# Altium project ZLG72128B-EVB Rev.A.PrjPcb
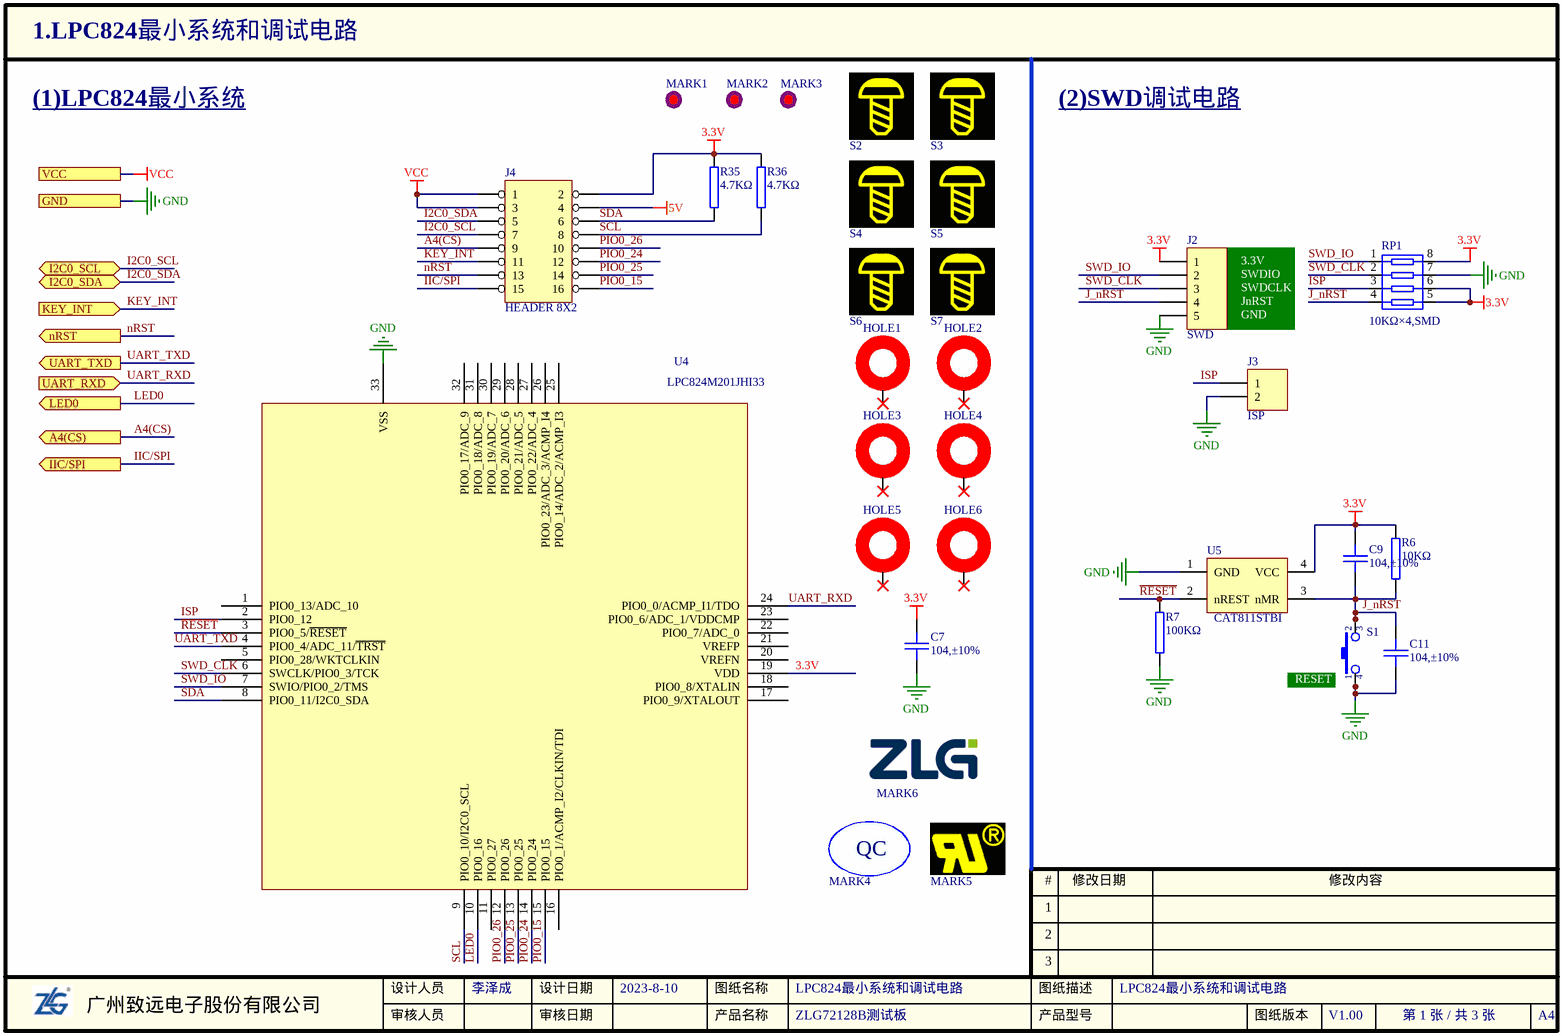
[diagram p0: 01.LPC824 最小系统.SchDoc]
3 sheets, 109 parts. Net scope: flat (ports and power ports of the same name join across sheets).
Board file: ZLG72128B-EVB Rev.A.PcbDoc
Sheets:
  01.LPC824 最小系统.SchDoc
  02.ZLG72128B-key-digital.SchDoc
  03.USB和电源.SchDoc

## Sheet 01.LPC824 最小系统.SchDoc
size A4; Author: 李泽成; DocumentNumber: 1; SheetNumber: 1; SheetTotal: 3; PageSetup: Record=PageOptions¦CenterHorizontal=True¦CenterVertical=True¦PrintScale=1.00¦XCorrection=1.00¦YCorrection=1.00¦PrintKind=0¦BorderSize=5000000¦LeftOffset=0¦BottomOffset=0¦Orientation=2¦PaperLength=1000¦PaperWidth=1000¦Scale=100¦PaperSource=7¦PrintQuality=600¦MediaType=1¦DitherType=10¦PaperKind=A4¦PrintScaleMode=1; DesignDate: 2023-8-10; SheetName: LPC824最小系统和调试电路; SheetVersion: V1.00; SheetDescription: LPC824最小系统和调试电路; ProductName: ZLG72128B测试板

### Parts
C7  104,±10%  [0603C]
C9  104,±10%  [0603C]
C11  104,±10%  [0603C]
HOLE1  HOLE  [HOLE-3.8]  (value not drawn)  (no BOM)
HOLE2  HOLE  [HOLE-3.8]  (value not drawn)  (no BOM)
HOLE3  HOLE  [HOLE-3.8]  (value not drawn)  (no BOM)
HOLE4  HOLE  [HOLE-3.8]  (value not drawn)  (no BOM)
HOLE5  HOLE  [HOLE-3.8]  (value not drawn)  (no BOM)
HOLE6  HOLE  [HOLE-3.8]  (value not drawn)  (no BOM)
J2  SWD  [SIP2.54-1X5]
J3  ISP  [SIP2.54-1X2]
J4  HEADER 8X2  [IDC-16-2.54]
MARK1  MARKER  [MARKER-C-1.0M]  (value not drawn)  (no BOM)
MARK2  MARKER  [MARKER-C-1.0M]  (value not drawn)  (no BOM)
MARK3  MARKER  [MARKER-C-1.0M]  (value not drawn)  (no BOM)
MARK4  ZY QC  [ZY_QC]  (value not drawn)  (no BOM)
MARK5  UR  [ZY_UR-3X2]  (value not drawn)  (no BOM)
MARK6  ZLGLOGO  [ZLG0.5]  (value not drawn)  (no BOM)
R6  10KΩ  [0603R]
R7  100KΩ  [0603R]
R35  4.7KΩ  [0603R]
R36  4.7KΩ  [0603R]
RP1  10KΩ×4,SMD  [0603RA]
S1  6×6×5.0mm,红色  [KEY-6S]  (value not drawn)
S2  (no value)  [Screw-Mark2]  (no BOM)
S3  (no value)  [Screw-Mark2]  (no BOM)
S4  (no value)  [Screw-Mark2]  (no BOM)
S5  (no value)  [Screw-Mark2]  (no BOM)
S6  (no value)  [Screw-Mark2]  (no BOM)
S7  (no value)  [Screw-Mark2]  (no BOM)
U4  LPC824M201JHI33  [QFN50P500X500X85-33N]
U5  value CAT811STBI  [SOT-143]  (hidden comment: CAT811)

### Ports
A4(CS) (out), GND, I2C0_SCL (bidir), I2C0_SDA (bidir), IIC/SPI (out), KEY_INT (in), LED0 (out), nRST (out), UART_RXD (in), UART_TXD (out), VCC

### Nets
3.3V: C7.2 C9.2 J2.1 J4.2 R6.2 R35.2 R36.2 RP1.5 RP1.6 RP1.8 U4.19(VDD) U5.4(VCC)
5V: J4.4
GND: C7.1 C11.1 J2.5 J3.2 R7.1 RP1.7 S1.1 S1.4 U4.33(VSS) U5.1(GND) ; port GND
VCC: J4.1 J4.3 ; port VCC
A4(CS): J4.9 ; port A4(CS)
I2C0_SCL: J4.7 ; port I2C0_SCL
I2C0_SDA: J4.5 ; port I2C0_SDA
IIC/SPI: J4.15 ; port IIC/SPI
ISP: J3.1 RP1.3 U4.2(PIO0_12)
J_nRST: C9.1 C11.2 J2.4 R6.1 RP1.4 S1.2 S1.3 U5.3(nMR)
KEY_INT: J4.11 ; port KEY_INT
LED0: U4.10(PIO0_16) ; port LED0
nRST: J4.13 ; port nRST
PIO0_15: J4.16 U4.15(PIO0_15)
PIO0_24: J4.12 U4.14(PIO0_24)
PIO0_25: J4.14 U4.13(PIO0_25)
PIO0_26: J4.10 U4.12(PIO0_26)
~{RESET}: R7.2 U4.3(PIO0_5/~{RESET}) U5.2(nREST)
SCL: J4.8 R36.1 U4.9(PIO0_10/I2C0_SCL)
SDA: J4.6 R35.1 U4.8(PIO0_11/I2C0_SDA)
SWD_CLK: J2.3 RP1.2 U4.6(SWCLK/PIO0_3/TCK)
SWD_IO: J2.2 RP1.1 U4.7(SWIO/PIO0_2/TMS)
UART_RXD: U4.24(PIO0_0/ACMP_I1/TDO) ; port UART_RXD
UART_TXD: U4.4(PIO0_4/ADC_11/~{TRST}) ; port UART_TXD

Not connected (* = marked no-connect by the designer): HOLE1 1*; HOLE2 1*; HOLE3 1*; HOLE4 1*; HOLE5 1*; HOLE6 1*; MARK1 0; MARK2 0; MARK3 0; U4 1(PIO0_13/ADC_10) 5(PIO0_28/WKTCLKIN) 11(PIO0_27) 16(PIO0_1/ACMP_I2/CLKIN/TDI) 17(PIO0_9/XTALOUT) 18(PIO0_8/XTALIN) 20(VREFN) 21(VREFP) 22(PIO0_7/ADC_0) 23(PIO0_6/ADC_1/VDDCMP) 25(PIO0_14/ADC_2/ACMP_I3) 26(PIO0_23/ADC_3/ACMP_I4) 27(PIO0_22/ADC_4) 28(PIO0_21/ADC_5) 29(PIO0_20/ADC_6) 30(PIO0_19/ADC_7) 31(PIO0_18/ADC_8) 32(PIO0_17/ADC_9)

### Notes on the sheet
- (1)LPC824最小系统
- (2)SWD调试电路
- (near R36) SCL
- 3.3V
- SWDIO
- SWDCLK
- JnRST
- GND
- (near S1) RESET

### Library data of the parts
C7 C9 C11 = 1.02.01.0032: 104,±10%,50V,X7R,0603,*,RoHS; 名称: 电容; 封装: 0603; 设备封装名称: C0603_104_X7R_50V_10%; 厂商: muRata; 贴片和直插: SMT; 器件优选方案: 量产物料,优先选用
J2 = Header 5H: Header, 5-Pin, Right Angle
J3 = Header 2H: Header, 2-Pin, Right Angle
MARK6 = ZLGLOGO: ZLGLIB
R6 = 1.01.01.0051: 10KΩ,0603,*,RoHS; 名称: 电阻; 封装: 0603; 设备封装名称: R0603_10K; 厂商: Ralec; 贴片和直插: SMT; 器件优选方案: 状态正常
R7 = 1.01.01.0062: 100KΩ,0603,*,RoHS; 名称: 电阻; 封装: 0603; 设备封装名称: R0603_100K; 厂商: Ralec; 贴片和直插: SMT; 器件优选方案: 状态正常
R35 R36 = 1.01.01.0045: 4.7KΩ,0603,*,RoHS; 名称: 电阻; 封装: 0603; 设备封装名称: R0603_4.7K; 厂商: Ralec; 贴片和直插: SMT; 器件优选方案: 正常状态，可以选用
RP1 = 1.01.04.0004: 10KΩ×4,SMD,PZ-4-0.8,RoHS; 名称: 网络电阻; 设备封装名称: 10K_4_0603; 贴片和直插: SMT
S1 = 1.09.01.0004: 6×6×5.0mm,红色,SMD,*; 名称: 轻触按键; 贴片和直插: SMT; 器件优选方案: 正常状态，可以选用
S2-S7 = Screw-Mark
U4 = 1.05.01.0105: LPC824M201JHI33,HVQFN-33,NXP,RoHS; 名称: IC; 贴片和直插: SMT; PCB备注: 151130mxz160506ZW; 器件优选方案: 量产物料,优先选用
U5 = 1.05.07.0023: CAT811STBI,SOT-143,ON,RoHS; 名称: IC; 设备封装名称: SOT-143_CAT811STBI; 贴片和直插: SMT; 器件优选方案: 状态正常

## Sheet 02.ZLG72128B-key-digital.SchDoc
size A4; CheckedBy: <审核日期>; Author: 李泽成; DocumentNumber: 2; SheetNumber: 2; SheetTotal: 3; PageSetup: Record=PageOptions|CenterHorizontal=True|CenterVertical=True|PrintScale=1.00|XCorrection=1.00|YCorrection=1.00|PrintKind=0|BorderSize=5000000|LeftOffset=0|BottomOffset=0|Orientation=2|PaperLength=1000|PaperWidth=1000|Scale=100|PaperSource=7|PrintQuality=600|MediaType=1|DitherType=10|PaperKind=A4|PrintScaleMode=1; DesignDate: 2023-8-10; CheckDate: <审核人员>; SheetName: ZLG72128B与按键显示; SheetVersion: <V1.00>; SheetDescription: ZLG72128B应用电路; ProductName: ZLG72128B测试板
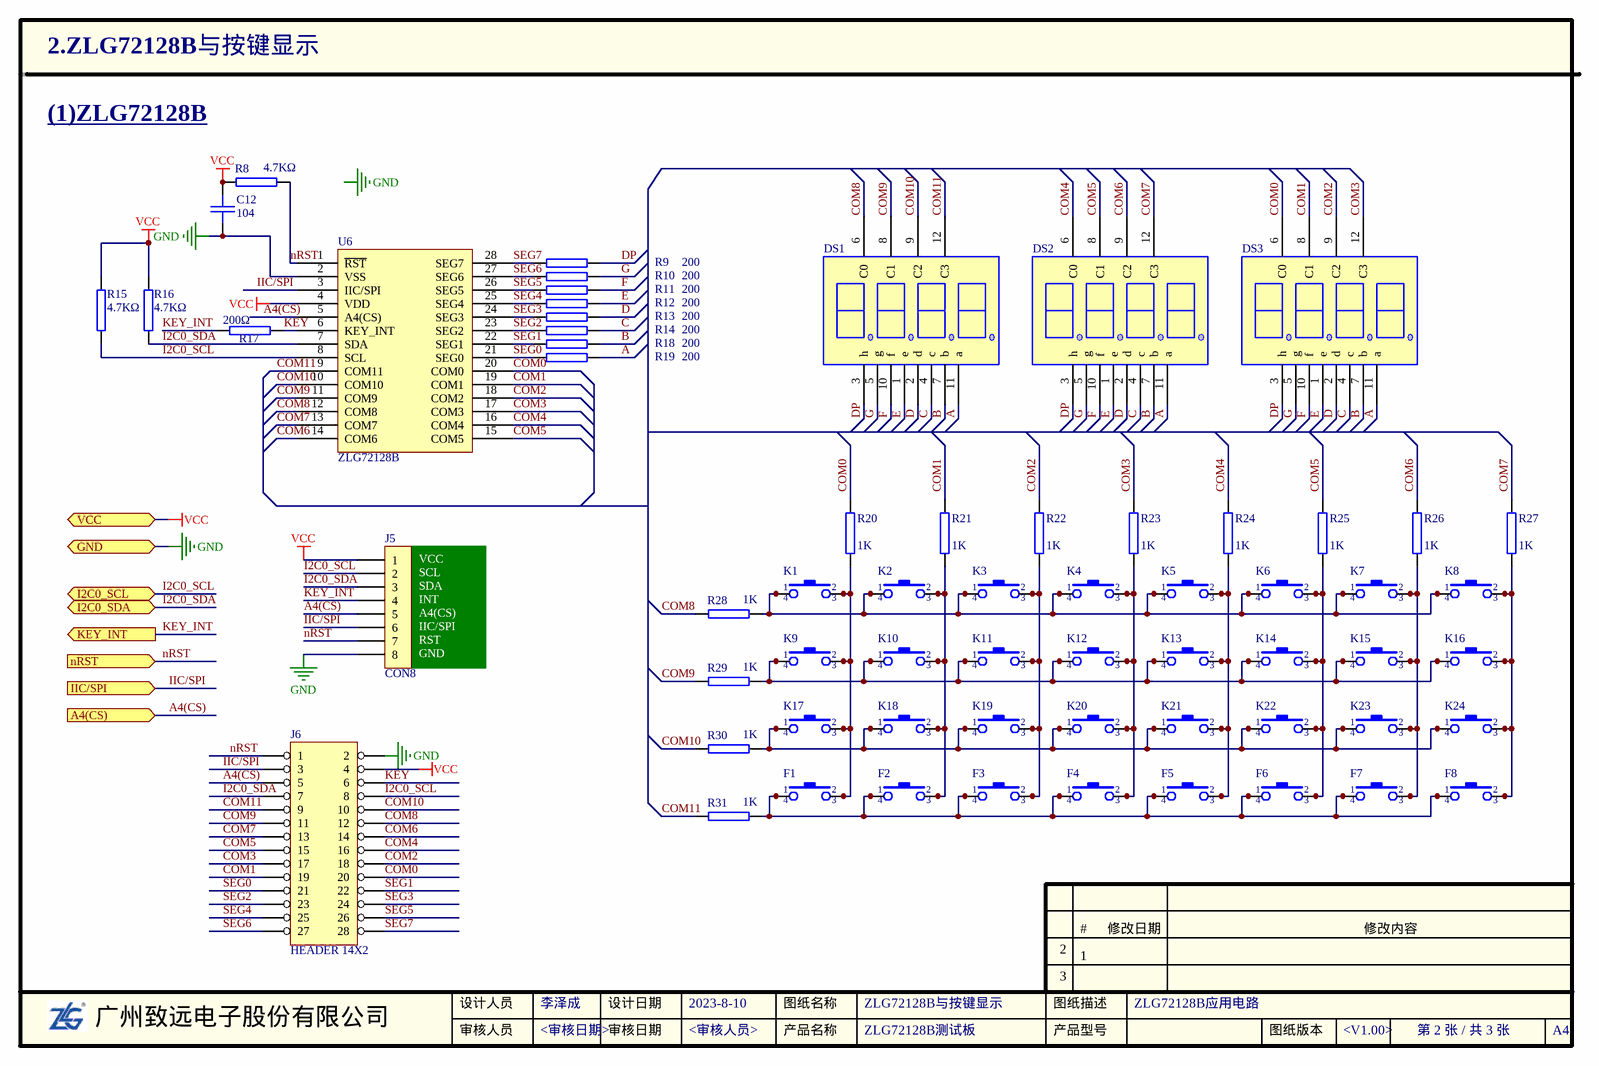
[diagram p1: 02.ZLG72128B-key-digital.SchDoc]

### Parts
C12  104  [0603C]
DS1  LN3461  [LN3461-3000X1400X720]  (value not drawn)
DS2  LN3461  [LN3461-3000X1400X720]  (value not drawn)
DS3  LN3461  [LN3461-3000X1400X720]  (value not drawn)
F1  6×6×5.0mm,红色  [KEY-6S]  (value not drawn)
F2  6×6×5.0mm,红色  [KEY-6S]  (value not drawn)
F3  6×6×5.0mm,红色  [KEY-6S]  (value not drawn)
F4  6×6×5.0mm,红色  [KEY-6S]  (value not drawn)
F5  6×6×5.0mm,红色  [KEY-6S]  (value not drawn)
F6  6×6×5.0mm,红色  [KEY-6S]  (value not drawn)
F7  6×6×5.0mm,红色  [KEY-6S]  (value not drawn)
F8  6×6×5.0mm,红色  [KEY-6S]  (value not drawn)
J5  CON8  [SIP-8-2.54]
J6  HEADER 14X2  [zlg72128]
K1  6×6×5.0mm,黑色  [KEY-6S]  (value not drawn)
K2  6×6×5.0mm,黑色  [KEY-6S]  (value not drawn)
K3  6×6×5.0mm,黑色  [KEY-6S]  (value not drawn)
K4  6×6×5.0mm,黑色  [KEY-6S]  (value not drawn)
K5  6×6×5.0mm,黑色  [KEY-6S]  (value not drawn)
K6  6×6×5.0mm,黑色  [KEY-6S]  (value not drawn)
K7  6×6×5.0mm,黑色  [KEY-6S]  (value not drawn)
K8  6×6×5.0mm,黑色  [KEY-6S]  (value not drawn)
K9  6×6×5.0mm,黑色  [KEY-6S]  (value not drawn)
K10  6×6×5.0mm,黑色  [KEY-6S]  (value not drawn)
K11  6×6×5.0mm,黑色  [KEY-6S]  (value not drawn)
K12  6×6×5.0mm,黑色  [KEY-6S]  (value not drawn)
K13  6×6×5.0mm,黑色  [KEY-6S]  (value not drawn)
K14  6×6×5.0mm,黑色  [KEY-6S]  (value not drawn)
K15  6×6×5.0mm,黑色  [KEY-6S]  (value not drawn)
K16  6×6×5.0mm,黑色  [KEY-6S]  (value not drawn)
K17  6×6×5.0mm,黑色  [KEY-6S]  (value not drawn)
K18  6×6×5.0mm,黑色  [KEY-6S]  (value not drawn)
K19  6×6×5.0mm,黑色  [KEY-6S]  (value not drawn)
K20  6×6×5.0mm,黑色  [KEY-6S]  (value not drawn)
K21  6×6×5.0mm,黑色  [KEY-6S]  (value not drawn)
K22  6×6×5.0mm,黑色  [KEY-6S]  (value not drawn)
K23  6×6×5.0mm,黑色  [KEY-6S]  (value not drawn)
K24  6×6×5.0mm,黑色  [KEY-6S]  (value not drawn)
R8  4.7KΩ  [0603R]
R9  200  [0805R]
R10  200  [0805R]
R11  200  [0805R]
R12  200  [0805R]
R13  200  [0805R]
R14  200  [0805R]
R15  4.7KΩ  [0603R]
R16  4.7KΩ  [0603R]
R17  200Ω  [0603R]
R18  200  [0805R]
R19  200  [0805R]
R20  1K  [0805R]
R21  1K  [0805R]
R22  1K  [0805R]
R23  1K  [0805R]
R24  1K  [0805R]
R25  1K  [0805R]
R26  1K  [0805R]
R27  1K  [0805R]
R28  1K  [0805R]
R29  1K  [0805R]
R30  1K  [0805R]
R31  1K  [0805R]
U6  ZLG72128B  [TSOP65P640X110-28N]

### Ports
A4(CS) (in), GND, I2C0_SCL (bidir), I2C0_SDA (bidir), IIC/SPI (in), KEY_INT (out), nRST (in), VCC

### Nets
GND: C12.1 J5.8 J6.2 U6.2(VSS) ; port GND
VCC: C12.2 J5.1 J6.4 R8.2 R15.2 R16.2 U6.4(VDD) ; port VCC
A: DS1.11(a) DS2.11(a) DS3.11(a) R19.2
A4(CS): J5.5 J6.5 U6.5(A4(CS)) ; port A4(CS)
B: DS1.7(b) DS2.7(b) DS3.7(b) R18.2
C: DS1.4(c) DS2.4(c) DS3.4(c) R14.2
COM0: DS3.6(C0) J6.20 R20.2 U6.20(COM0)
COM1: DS3.8(C1) J6.19 R21.2 U6.19(COM1)
COM2: DS3.9(C2) J6.18 R22.2 U6.18(COM2)
COM3: DS3.12(C3) J6.17 R23.2 U6.17(COM3)
COM4: DS2.6(C0) J6.16 R24.2 U6.16(COM4)
COM5: DS2.8(C1) J6.15 R25.2 U6.15(COM5)
COM6: DS2.9(C2) J6.14 R26.2 U6.14(COM6)
COM7: DS2.12(C3) J6.13 R27.2 U6.13(COM7)
COM8: DS1.6(C0) J6.12 R28.1 U6.12(COM8)
COM9: DS1.8(C1) J6.11 R29.1 U6.11(COM9)
COM10: DS1.9(C2) J6.10 R30.1 U6.10(COM10)
COM11: DS1.12(C3) J6.9 R31.1 U6.9(COM11)
D: DS1.2(d) DS2.2(d) DS3.2(d) R13.2
DP: DS1.3(h) DS2.3(h) DS3.3(h) R9.2
E: DS1.1(e) DS2.1(e) DS3.1(e) R12.2
F: DS1.10(f) DS2.10(f) DS3.10(f) R11.2
G: DS1.5(g) DS2.5(g) DS3.5(g) R10.2
I2C0_SCL: J5.2 J6.8 R15.1 U6.8(SCL) ; port I2C0_SCL
I2C0_SDA: J5.3 J6.7 R16.1 U6.7(SDA) ; port I2C0_SDA
IIC/SPI: J5.6 J6.3 U6.3(IIC/SPI) ; port IIC/SPI
KEY: J6.6 R17.2 U6.6(KEY_INT)
KEY_INT: J5.4 R17.1 ; port KEY_INT
nRST: J5.7 J6.1 R8.1 U6.1(~{RST}) ; port nRST
SEG0: J6.21 R19.1 U6.21(SEG0)
SEG1: J6.22 R18.1 U6.22(SEG1)
SEG2: J6.23 R14.1 U6.23(SEG2)
SEG3: J6.24 R13.1 U6.24(SEG3)
SEG4: J6.25 R12.1 U6.25(SEG4)
SEG5: J6.26 R11.1 U6.26(SEG5)
SEG6: J6.27 R10.1 U6.27(SEG6)
SEG7: J6.28 R9.1 U6.28(SEG7)
NetF1_1: F1.1 F1.4 F2.1 F2.4 F3.1 F3.4 F4.1 F4.4 F5.1 F5.4 F6.1 F6.4 F7.1 F7.4 F8.1 F8.4 R31.2
NetF1_2: F1.2 F1.3 K1.2 K1.3 K9.2 K9.3 K17.2 K17.3 R20.1
NetF2_2: F2.2 F2.3 K2.2 K2.3 K10.2 K10.3 K18.2 K18.3 R21.1
NetF3_2: F3.2 F3.3 K3.2 K3.3 K11.2 K11.3 K19.2 K19.3 R22.1
NetF4_2: F4.2 F4.3 K4.2 K4.3 K12.2 K12.3 K20.2 K20.3 R23.1
NetF5_2: F5.2 F5.3 K5.2 K5.3 K13.2 K13.3 K21.2 K21.3 R24.1
NetF6_2: F6.2 F6.3 K6.2 K6.3 K14.2 K14.3 K22.2 K22.3 R25.1
NetF7_2: F7.2 F7.3 K7.2 K7.3 K15.2 K15.3 K23.2 K23.3 R26.1
NetF8_2: F8.2 F8.3 K8.2 K8.3 K16.2 K16.3 K24.2 K24.3 R27.1
NetK1_1: K1.1 K1.4 K2.1 K2.4 K3.1 K3.4 K4.1 K4.4 K5.1 K5.4 K6.1 K6.4 K7.1 K7.4 K8.1 K8.4 R28.2
NetK9_1: K9.1 K9.4 K10.1 K10.4 K11.1 K11.4 K12.1 K12.4 K13.1 K13.4 K14.1 K14.4 K15.1 K15.4 K16.1 K16.4 R29.2
NetK17_1: K17.1 K17.4 K18.1 K18.4 K19.1 K19.4 K20.1 K20.4 K21.1 K21.4 K22.1 K22.4 K23.1 K23.4 K24.1 K24.4 R30.2

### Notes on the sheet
- (1)ZLG72128B
- (near J5) SCL
- (near J5) SDA
- (near J5) VCC
- (near J5) INT
- (near J5) RST
- (near J5) A4(CS)
- (near J5) GND
- (near J5) IIC/SPI
- #
- 修改日期
- 修改内容
- 2
- 3
- 1
- 广州致远电子股份有限公司
- 设计人员
- 审核人员
- 设计日期
- 审核日期
- 产品名称
- 图纸名称
- 产品型号
- 图纸描述
- 图纸版本
- A4
- Labels drawn without touching a wire or pin: GND

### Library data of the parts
C12 = 1.02.01.0032: as C7 on sheet 01.LPC824 最小系统
DS1-DS3 = 1.08.01.0003: LN3461AS,30×14×7.3mm,四位共阴,RoHS; 名称: 数码管; 贴片和直插: THT; PCB备注: 焊盘孔径改为0.8mm，外形丝印改变，两排焊盘间间距改为10.36，Fwrj-Shcj-Tlq-141224
F1-F8 = 1.09.01.0004: as S1 on sheet 01.LPC824 最小系统
J5 = CON8: Connector
K1-K24 = 1.09.01.0003: 6×6×5.0mm,黑色,SMD,,*; 名称: 轻触按键; 贴片和直插: SMT; 器件优选方案: 正常状态，可以选用
R8 R15 R16 = 1.01.01.0045: 4.7KΩ,0603,*,RoHS; 名称: 电阻; 封装: 0603; 设备封装名称: R0603_4.7K; 厂商: Ralec; 贴片和直插: SMT; 器件优选方案: 状态正常
R9-R14 R18 R19 = 1.01.02.0121: 200Ω,±1%,0805,*,RoHS; 名称: 电阻; 封装: 0805; 设备封装名称: R0805_200R_1%; 厂商: Ralec; 贴片和直插: SMT
R17 = 1.01.01.0026: 200Ω,0603,*,RoHS; 名称: 电阻; 封装: 0603; 设备封装名称: R0603_200R; 厂商: Ralec; 贴片和直插: SMT; 器件优选方案: 状态正常
R20-R31 = 1.01.02.0045: 1KΩ,±1%,0805,*,RoHS; Value: 1KΩ,±1%; 名称: 电阻; 封装: 0805; 设备封装名称: R0805_1K_1%; 厂商: Ralec; 贴片和直插: SMT

## Sheet 03.USB和电源.SchDoc
size A4; Author: 李泽成; DocumentNumber: 3; SheetNumber: 3; SheetTotal: 3; PageSetup: Record=PageOptions|CenterHorizontal=True|CenterVertical=True|PrintScale=1.00|XCorrection=1.00|YCorrection=1.00|PrintKind=0|BorderSize=5000000|LeftOffset=0|BottomOffset=0|Orientation=2|PaperLength=1000|PaperWidth=1000|Scale=100|PaperSource=7|PrintQuality=600|MediaType=1|DitherType=10|PaperKind=A4|PrintScaleMode=1; DesignDate: 2023-8-10; SheetName: USB转串口和电源; SheetVersion: V1.00; SheetDescription: USB转串口和电源; ProductName: ZLG72128B测试板
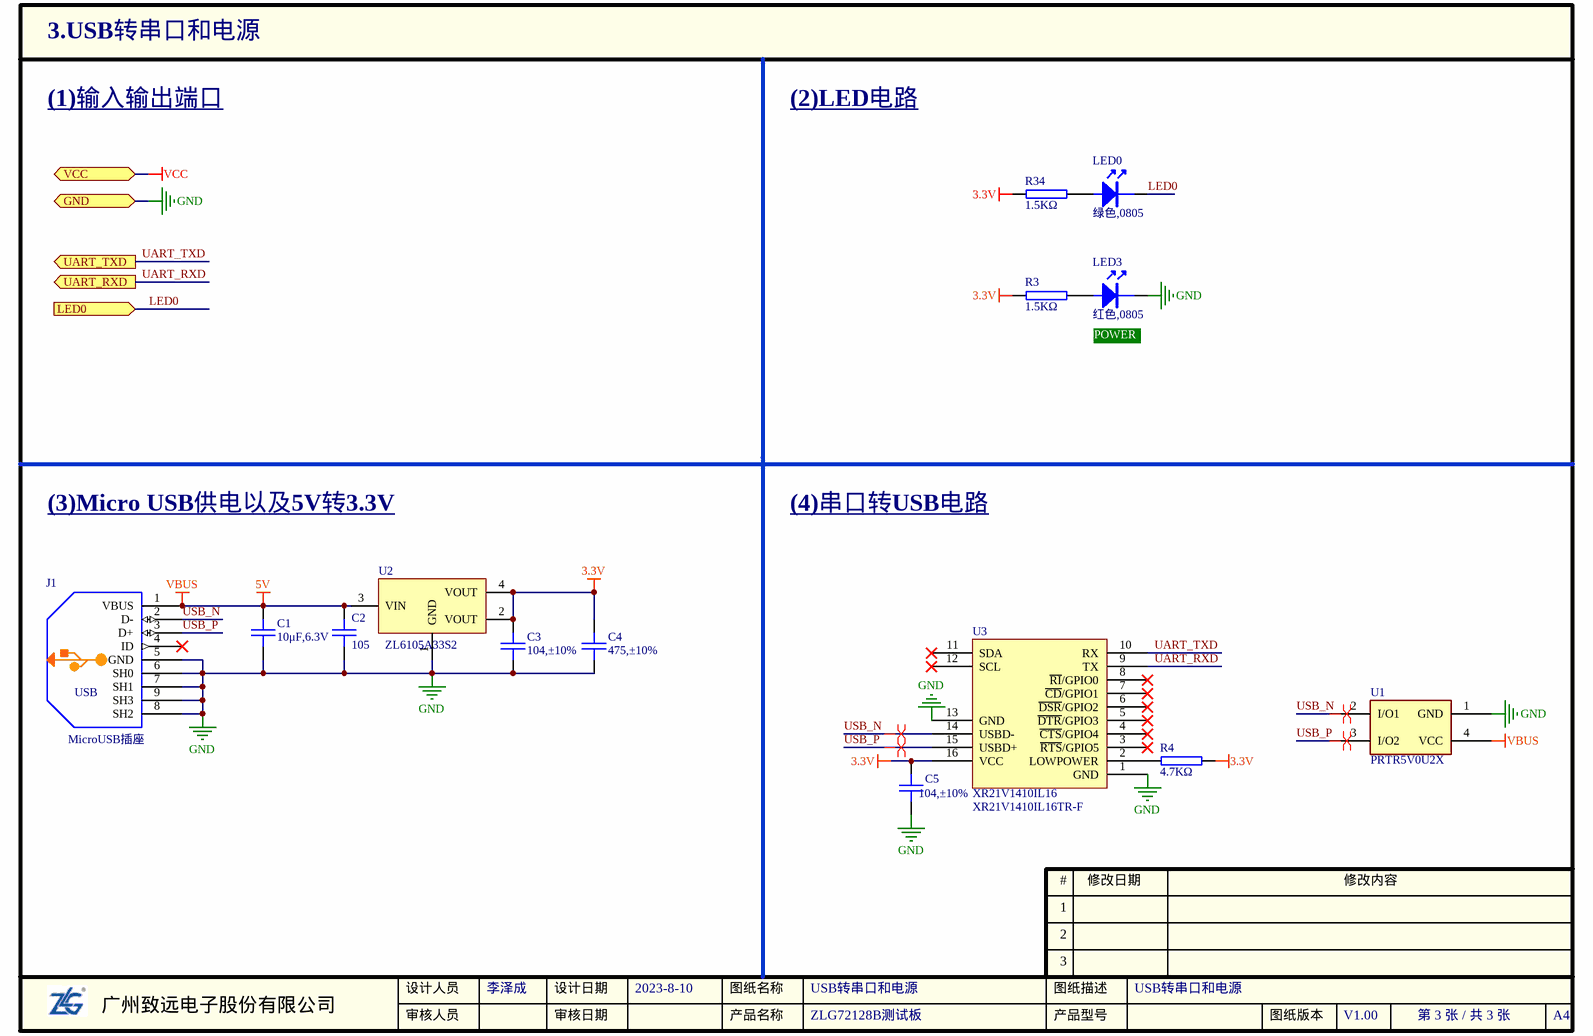
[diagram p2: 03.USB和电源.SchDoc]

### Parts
C1  10μF,6.3V  [0603C]
C2  105  [0805C]
C3  104,±10%  [0603C]
C4  475,±10%  [0805C]
C5  104,±10%  [0603C]
J1  value MicroUSB插座  [MICROUSB-5S]  (hidden comment: USB_MINIB_SMT)
LED0  value 绿色,0805  [LED-0805]  (hidden comment: LED0)
LED3  value 红色,0805  [LED-0805]  (hidden comment: LED1)
R3  1.5KΩ  [0603R]
R4  4.7KΩ  [0603R]
R34  1.5KΩ  [0603R]
U1  PRTR5V0U2X  [SOT-143]
U2  ZL6105A33S2  [SOT229P700X180-4N]
U3  XR21V1410IL16  value XR21V1410IL16TR-F  [QFN50P300X300X80-17AN]

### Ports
GND, LED0 (in), UART_RXD (out), UART_TXD (out), VCC

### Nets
3.3V: C3.2 C4.1 C5.1 R3.1 R4.1 R34.2 U2.2(VOUT) U2.4(VOUT) U3.16(VCC)
5V: C1.1 C2.2 J1.1(VBUS) U1.4(VCC) U2.3(VIN)  [also labelled VBUS]
GND: C1.2 C2.1 C3.1 C4.2 C5.2 J1.5(GND) J1.6(SH0) J1.7(SH1) J1.8(SH2) J1.9(SH3) LED3.2 U1.1(GND) U2.1(GND) U3.1(GND) U3.13(GND) ; port GND
LED0: LED0.2 ; port LED0
UART_RXD: U3.9(TX) ; port UART_RXD
UART_TXD: U3.10(RX) ; port UART_TXD
USB_N: J1.2(D-) U1.2(I/O1) U3.14(USBD-)
USB_P: J1.3(D+) U1.3(I/O2) U3.15(USBD+)
NetLED0_1: LED0.1 R34.1
NetLED3_1: LED3.1 R3.2
NetR4_2: R4.2 U3.2(LOWPOWER)

Not connected (* = marked no-connect by the designer): J1 4(ID)*; U3 3(~{RTS}/GPIO5)* 4(~{CTS}/GPIO4)* 5(~{DTR}/GPIO3)* 6(~{DSR}/GPIO2)* 7(~{CD}/GPIO1)* 8(~{RI}/GPIO0)* 11(SDA)* 12(SCL)*

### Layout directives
differential pair: USB_N, USB_P

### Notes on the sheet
- (1)输入输出端口
- (2)LED电路
- RESET
- POWER
- (3)Micro USB供电以及5V转3.3V
- (4)串口转USB电路

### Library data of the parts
C1 = 1.02.01.0065: 10μF,6.3V,X5R,GRM188R60J106M****,0603,Murata,RoHS; 名称: 电容; 封装: 0603; 贴片和直插: SMT; 器件优选方案: 状态正常
C2 = 1.02.02.0044: C2012X7R1E105KT000N,105,±10%,25V,X7R,0805,TDK,RoHS; 名称: 电容; 封装: 0805; 设备封装名称: C0805_105_X7R_25V_10%; 贴片和直插: SMT; 器件优选方案: 量产物料,优先选用
C3 C5 = 1.02.01.0032: as C7 on sheet 01.LPC824 最小系统
C4 = 1.02.02.0064: 475,±10%,16V,X7R,0805,RoHS; 名称: 电容; 封装: 0805; 设备封装名称: C0805_475_X7R_16V_10%; 贴片和直插: SMT; 器件优选方案: 量产物料,优先选用
J1 = USB_MINIB_SMT: A01SB141B1-261,MicroUSB插座,SMT,艾立信,RoHS; Text Field1: 100; Text Field2: 80; 物料代码: 1.10.12.0014; PCB备注: 141030lmd; 器件优选方案: 样品物料,谨慎选用
LED0 = 1.04.05.0002: 绿色,0805,0805,RoHS; 名称: 发光二极管; 封装: 0805; 设备封装名称: LED0805-GREEN; 贴片和直插: SMT; 器件优选方案: 样品物料,谨慎选用
LED3 = 1.04.05.0001: 红色,0805,0805,RoHS; 名称: 发光二极管; 封装: 0805; 设备封装名称: LED0805-RED; 贴片和直插: SMT; 器件优选方案: 样品物料,谨慎选用
R3 R34 = 1.01.01.0037: 1.5KΩ,0603,*,RoHS; 名称: 电阻; 封装: 0603; 设备封装名称: R0603_1.5K; 厂商: Ralec; 贴片和直插: SMT; 器件优选方案: 状态正常
R4 = 1.01.01.0045: as R8 on sheet 02.ZLG72128B-key-digital
U1 = 1.05.10.0153: PRTR5V0U2X,SOT-143B,NXP,RoHS; 名称: IC; 设备封装名称: SOT-143B_PRTR5V0U2X; 贴片和直插: SMT
U2 = 89.12.00022: 名称: 集成电路; 封装: SOT-223; 厂商: ZHIYUAN; 贴片和直插: SMT; PCB备注: 200102ZW; 器件优选方案: 推荐使用; 生产单位: PCS
U3 = 1.05.08.0043: XR21V1410IL16TR-F,QFN-16,EXAR; 名称: IC; 设备封装名称: QFN-16_XR21V1410IL16; 贴片和直插: SMT

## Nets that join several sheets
3.3V: 01.LPC824 最小系统 (12 pins), 03.USB和电源 (9 pins)
5V: 01.LPC824 最小系统 (J4.4), 03.USB和电源 (5 pins)
GND: 01.LPC824 最小系统 (10 pins), 02.ZLG72128B-key-digital (C12.1 J5.8 J6.2 U6.2), 03.USB和电源 (15 pins)
VCC: 01.LPC824 最小系统 (J4.1 J4.3), 02.ZLG72128B-key-digital (7 pins)
A4(CS): 01.LPC824 最小系统 (J4.9), 02.ZLG72128B-key-digital (J5.5 J6.5 U6.5)
I2C0_SCL: 01.LPC824 最小系统 (J4.7), 02.ZLG72128B-key-digital (J5.2 J6.8 R15.1 U6.8)
I2C0_SDA: 01.LPC824 最小系统 (J4.5), 02.ZLG72128B-key-digital (J5.3 J6.7 R16.1 U6.7)
IIC/SPI: 01.LPC824 最小系统 (J4.15), 02.ZLG72128B-key-digital (J5.6 J6.3 U6.3)
KEY_INT: 01.LPC824 最小系统 (J4.11), 02.ZLG72128B-key-digital (J5.4 R17.1)
LED0: 01.LPC824 最小系统 (U4.10), 03.USB和电源 (LED0.2)
nRST: 01.LPC824 最小系统 (J4.13), 02.ZLG72128B-key-digital (J5.7 J6.1 R8.1 U6.1)
UART_RXD: 01.LPC824 最小系统 (U4.24), 03.USB和电源 (U3.9)
UART_TXD: 01.LPC824 最小系统 (U4.4), 03.USB和电源 (U3.10)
